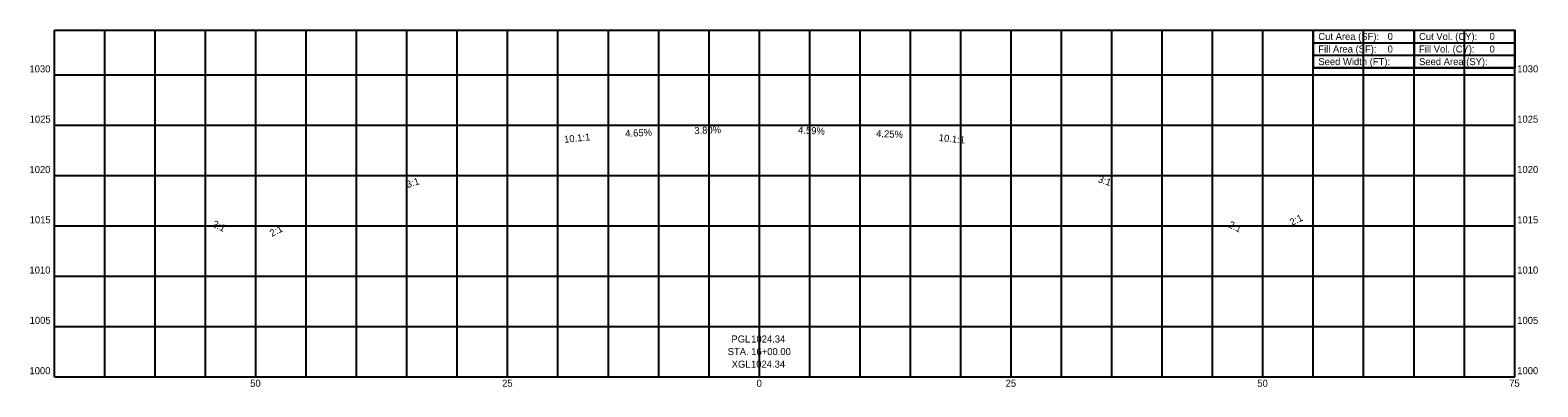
# Model space of a CAD drawing. Extents: x -72 to 77, y 999 to 1034.
import ezdxf

# ---------------------------------------------------------------- set-up
doc = ezdxf.new("R2010")
doc.units = 0
for name, color, linetype in [('Default', 7, 'Continuous'), ('DT_X_Break_Line', 7, 'Continuous'), ('DT_X_Spot_Elev', 7, 'Continuous'), ('DT_X_Void', 7, 'Continuous'), ('SH_Data', 7, 'Continuous')]:
    doc.layers.add(name, color=color, linetype=linetype)

msp = doc.modelspace()

# ---------------------------------------------------------------- linework, layer by layer
at = {"layer": 'Default'}
msp.add_circle((75, 1034.45), 0.000417, dxfattribs=at)
msp.add_circle((75, 1034.45), 0.000417, dxfattribs=at)
msp.add_circle((75, 1034.45), 0.000417, dxfattribs=at)
msp.add_circle((75, 1034.45), 0.000417, dxfattribs=at)
msp.add_circle((75, 1034.45), 0.000417, dxfattribs=at)
msp.add_circle((75, 1034.45), 0.000417, dxfattribs=at)
msp.add_circle((75, 1034.45), 0.000417, dxfattribs=at)
msp.add_circle((75, 1034.45), 0.000417, dxfattribs=at)
msp.add_circle((75, 1034.45), 0.000417, dxfattribs=at)
msp.add_circle((75, 1034.45), 0.000417, dxfattribs=at)
msp.add_circle((75, 1034.45), 0.000417, dxfattribs=at)
msp.add_circle((75, 1034.45), 0.000417, dxfattribs=at)
at = {"layer": 'DT_X_Break_Line'}
for p, q in [((-70, 1034.45), (75, 1034.45)), ((-70, 1000), (-70, 1034.45)), ((-65, 1000), (-65, 1034.45)), ((-60, 1000), (-60, 1034.45)), ((-55, 1000), (-55, 1034.45)), ((-50, 1000), (-50, 1034.45)), ((-45, 1000), (-45, 1034.45)), ((-40, 1000), (-40, 1034.45)), ((-35, 1000), (-35, 1034.45)), ((-30, 1000), (-30, 1034.45)), ((-25, 1000), (-25, 1034.45)), ((-20, 1000), (-20, 1034.45)), ((-15, 1000), (-15, 1034.45)), ((-10, 1000), (-10, 1034.45)), ((-5, 1000), (-5, 1034.45)), ((0, 1000), (0, 1034.45)), ((5, 1000), (5, 1034.45)), ((10, 1000), (10, 1034.45)), ((15, 1000), (15, 1034.45)), ((20, 1000), (20, 1034.45)), ((25, 1000), (25, 1034.45)), ((30, 1000), (30, 1034.45)), ((35, 1000), (35, 1034.45)), ((40, 1000), (40, 1034.45)), ((45, 1000), (45, 1034.45)), ((50, 1000), (50, 1034.45)), ((55, 1000), (55, 1034.45)), ((60, 1000), (60, 1034.45)), ((65, 1000), (65, 1034.45)), ((70, 1000), (70, 1034.45)), ((75, 1000), (75, 1034.45)), ((-70, 1030), (75, 1030)), ((-70, 1025), (75, 1025)), ((-70, 1020), (75, 1020)), ((-70, 1015), (75, 1015)), ((-70, 1010), (75, 1010)), ((-70, 1005), (75, 1005)), ((-70, 1000), (75, 1000))]:
    msp.add_line(p, q, dxfattribs=at)
at = {"layer": 'DT_X_Void'}
msp.add_lwpolyline([(55, 1034.45), (75, 1034.45), (75, 1030.7), (55, 1030.7)], close=True, dxfattribs=at)
at = {"layer": 'SH_Data'}
for p, q in [((55, 1034.45), (75, 1034.45)), ((55, 1034.45), (55, 1031.95)), ((55, 1033.2), (75, 1033.2)), ((65, 1034.45), (65, 1030.7)), ((75, 1034.45), (75, 1031.95)), ((55, 1031.95), (75, 1031.95)), ((63.3, 1031.32), (63.3, 1031.32)), ((72.95, 1031.32), (72.95, 1031.32))]:
    msp.add_line(p, q, dxfattribs=at)
msp.add_lwpolyline([(55, 1031.95), (55, 1030.7), (75, 1030.7), (75, 1031.95)], dxfattribs=at)

# ---------------------------------------------------------------- texts
at = {"layer": 'DT_X_Spot_Elev'}
for s, p in [('Cut Area (SF):', (55.5, 1033.47)), ('0', (62.38, 1033.47)), ('Cut Vol. (CY):', (65.5, 1033.47)), ('0', (72.5, 1033.47)), ('Seed Width (FT):', (55.5, 1030.97)), ('Fill Area (SF):', (55.5, 1032.22)), ('0', (62.38, 1032.22)), ('Seed Area (SY):', (65.5, 1030.97)), ('Fill Vol. (CY):', (65.5, 1032.22)), ('0', (72.5, 1032.22)), ('1030', (-72.48, 1030.25)), ('1030', (75.25, 1030.25)), ('1025', (-72.46, 1025.25)), ('1025', (75.25, 1025.25)), ('1020', (-72.48, 1020.25)), ('1020', (75.25, 1020.25)), ('1015', (-72.46, 1015.25)), ('1015', (75.25, 1015.25)), ('1010', (-72.48, 1010.25)), ('1010', (75.25, 1010.25)), ('1005', (-72.46, 1005.25)), ('1005', (75.25, 1005.25)), ('PGL ', (-2.78, 1003.4)), ('1024.34', (-0.81, 1003.4)), ('STA. 16+00.00', (-3.15, 1002.15)), ('XGL ', (-2.75, 1000.9)), ('1024.34', (-0.83, 1000.9)), ('1000', (-72.48, 1000.25)), ('1000', (75.25, 1000.25)), ('50', (-50.56, 999)), ('25', (-25.55, 999)), ('0', (-0.28, 999)), ('25', (24.45, 999)), ('50', (49.44, 999)), ('75', (74.45, 999))]:
    msp.add_text(s, height=0.7, dxfattribs=at).set_placement(p)
for s, rotation, p in [('10.1:1', 5.6655, (-19.36, 1023.24)), ('4.65%', 2.6641, (-13.31, 1023.83)), ('3.80%', 2.1769, (-6.45, 1024.11)), ('4.59%', 357.3713, (3.83, 1024.18)), ('4.25%', 357.5681, (11.58, 1023.83)), ('10.1:1', 354.331, (17.79, 1023.43)), ('3:1', 18.4114, (-34.93, 1018.74)), ('3:1', 341.6154, (33.56, 1019.35)), ('2:1', 333.4892, (-54.39, 1014.96)), ('2:1', 26.543, (-48.42, 1013.89)), ('2:1', 333.4561, (46.5, 1014.89)), ('2:1', 26.5248, (52.87, 1014.98))]:
    msp.add_text(s, height=0.7, rotation=rotation, dxfattribs=at).set_placement(p)

doc.saveas('drawing.dxf')
